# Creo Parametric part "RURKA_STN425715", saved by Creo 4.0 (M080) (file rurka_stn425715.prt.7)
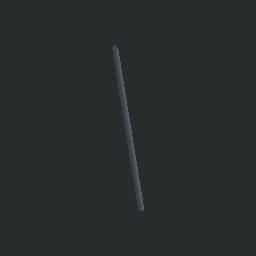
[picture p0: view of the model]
Units: millimeter Kilogram Sec (mmKs); MM, KILOGRAM, SECS
Materials in the file: OCEL_N

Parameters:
  MFG_WP_MATERIAL = "OCEL"
  NAZOV = "RURKA_STN425715"
  NORMA = "STN 42 5715"
  NAZOV_1 = "START_PART_IPM"
  PTC_MATERIAL_NAME = "OCEL_N"

Other parameters: HMOTNOST, HUSTOTA, HMOTNOST_1, HUSTOTA_1

Created from: P425715.PRT

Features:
  1. datum plane "DTM1"
  2. datum plane "DTM2"
  3. datum plane "DTM3"
  4. coordinate system
  5. protrusion

Other named items: CS0

Layers: 1, 2, 3, 4, 5, 6, 7, 8, 9, 10, 11, 12, 13, 14, 15, 16, 17, 18, 19, 20, 21, 22, 23, 24, 25, 26, 27, 28, 29, 30, 31, 32

Family table entries: GENERIC, RURKA_TR_22X2_6, RURKA_STN425715, value(d_val), value(i_val), RURKA_TR_25X2_6, RURKA_STN425715, !/9, RURKA_TR_25X3_2, RURKA_STN425715, !/9, RURKA_TR_28X2_6, RURKA_STN425715, !/<, RURKA_TR_28X3_2, RURKA_STN425715, !/<, RURKA_TR_28X4, RURKA_STN425715, !/<, RURKA_TR_31_8X2_6, RURKA_STN425715, !/?, RURKA_TR_31_8X3_2, RURKA_STN425715, !/?, RURKA_TR_31_8X4, RURKA_STN425715, !/?, RURKA_TR_35X2_6, RURKA_STN425715, RURKA_TR_35X4, RURKA_STN425715, RURKA_TR_35X5, RURKA_STN425715, RURKA_TR_38X4, RURKA_STN425715, !/C, RURKA_TR_44_5X2_6, RURKA_STN425715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

Surfaces: 2 plane, 2 cylinder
